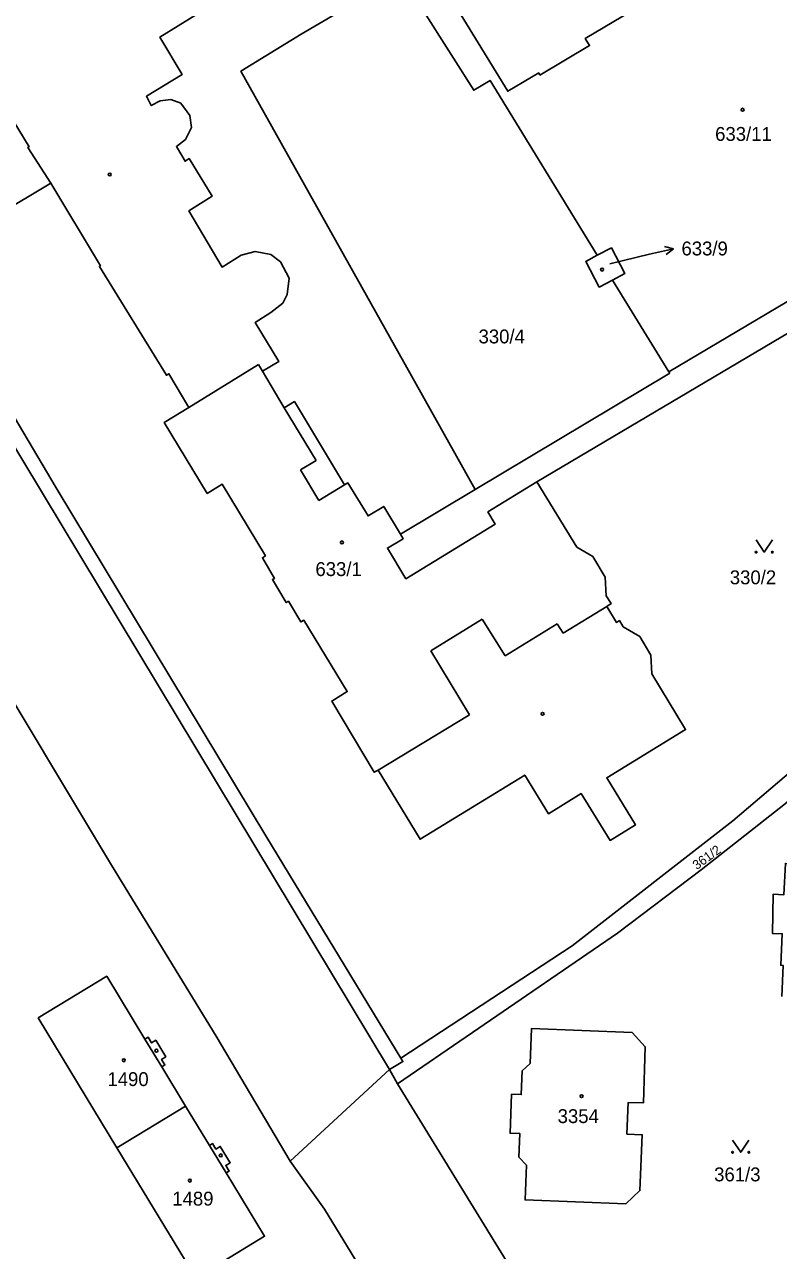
# Model space of a CAD drawing. Extents: x -679220 to -673243, y -1075091 to -1066557.
# Drawn here: x -675835 to -675742.5, y -1072476.3 to -1072325.9 of the extents above; entities that cross this region are included whole.
import ezdxf

# ---------------------------------------------------------------- set-up
doc = ezdxf.new("R2010")
doc.units = 0
for name, color, linetype in [('Hranice parcel', 7, 'Continuous'), ('Parcelní čísla', 7, 'Continuous'), ('Pop  PČ popisy', 7, 'Continuous'), ('Vnitřní kresba', 7, 'Continuous'), ('Značky budov', 7, 'Continuous'), ('Značky kultur', 7, 'Continuous')]:
    doc.layers.add(name, color=color, linetype=linetype)

msp = doc.modelspace()

# ---------------------------------------------------------------- linework, layer by layer
at = {"layer": 'Hranice parcel'}
for p, q in [((-675847.7, -1072354.86), (-675831.76, -1072345.39)), ((-675755.91, -1072368.55), (-675725.02, -1072350.17)), ((-675762.83, -1072357.28), (-675755.91, -1072368.55)), ((-675736.86, -1072361.17), (-675772.1, -1072382.03)), ((-675779.67, -1072382.96), (-675755.81, -1072368.71)), ((-675755.81, -1072368.71), (-675755.91, -1072368.55)), ((-675788.85, -1072388.44), (-675779.67, -1072382.96)), ((-675802.38, -1072465.38), (-675790.19, -1072454.14)), ((-675790.19, -1072454.14), (-675789.23, -1072455.87)), ((-675815.23, -1072458.61), (-675823.65, -1072463.72)), ((-675813.96, -1072479.68), (-675823.65, -1072463.72))]:
    msp.add_line(p, q, dxfattribs=at)
for points in [[(-675990.34, -1072122.74), (-675965.06, -1072164.5), (-675944.22, -1072198.66), (-675920.45, -1072238.88), (-675899.68, -1072273.04), (-675879.13, -1072306.74), (-675849.47, -1072355.79), (-675790.19, -1072454.14)], [(-675826.14, -1072308.69), (-675826.56, -1072309.22), (-675827.19, -1072309.93), (-675827.57, -1072310.88), (-675827.69, -1072311.75), (-675827.52, -1072312.73), (-675827.33, -1072313.58), (-675827.04, -1072314.06), (-675844.34, -1072324.49), (-675839.1, -1072333.23), (-675839.42, -1072333.42), (-675837.28, -1072336.95), (-675836.95, -1072336.77), (-675834.44, -1072340.93), (-675834.58, -1072341.01), (-675831.76, -1072345.39)], [(-675771.74, -1072332.13), (-675771.88, -1072331.88), (-675775.68, -1072334.13), (-675782.18, -1072323.54), (-675770.47, -1072316.51), (-675770.14, -1072317.05), (-675763.67, -1072313.14), (-675762.01, -1072315.74), (-675756.31, -1072312.33), (-675755.8, -1072313.14), (-675751.43, -1072310.59), (-675747.8, -1072316.66), (-675752.12, -1072319.31), (-675751.64, -1072320.13), (-675757.74, -1072323.78), (-675758.24, -1072322.9), (-675766.17, -1072327.66), (-675765.65, -1072328.52), (-675771.74, -1072332.13)], [(-675779.67, -1072382.96), (-675808.43, -1072331.67), (-675801.04, -1072327.14), (-675788.52, -1072319.77)], [(-675813.87, -1072324.69), (-675818.38, -1072327.47), (-675815.63, -1072332.06), (-675820.04, -1072334.74), (-675819.45, -1072335.88), (-675818.34, -1072335.31), (-675817.03, -1072335.13), (-675815.82, -1072335.58), (-675814.69, -1072337.1), (-675814.51, -1072338.55), (-675815.25, -1072340.06), (-675816.35, -1072340.91), (-675815.3, -1072342.71), (-675814.79, -1072342.39), (-675811.96, -1072346.98), (-675814.81, -1072348.8), (-675810.74, -1072355.7), (-675808.42, -1072354.25), (-675806.68, -1072353.78), (-675804.75, -1072354.16), (-675803.58, -1072355.05), (-675802.53, -1072357.04), (-675802.76, -1072359.06), (-675803.3, -1072360.11), (-675804.76, -1072361.28), (-675806.67, -1072362.48), (-675803.77, -1072367.26), (-675805.79, -1072368.46), (-675803.13, -1072372.94), (-675801.86, -1072372.18), (-675795.73, -1072382.42), (-675795.31, -1072382.17), (-675792.82, -1072386.21), (-675790.9, -1072385.04), (-675788.85, -1072388.44)], [(-675785.98, -1072324.32), (-675779.85, -1072333.99), (-675777.86, -1072332.8), (-675764.69, -1072354.25)], [(-675831.76, -1072345.39), (-675825.68, -1072355.53), (-675825.8, -1072355.6), (-675817.58, -1072368.95), (-675817.27, -1072368.77), (-675814.82, -1072372.9), (-675817.84, -1072374.76), (-675812.57, -1072383.46), (-675810.72, -1072382.32), (-675805.43, -1072391.12), (-675805.8, -1072391.34), (-675804.33, -1072393.89), (-675804.58, -1072394.03), (-675802.88, -1072396.84), (-675802.61, -1072396.68), (-675801.07, -1072399.22), (-675800.7, -1072399.01), (-675795.39, -1072407.77), (-675797.29, -1072408.92), (-675792.07, -1072417.66), (-675791.6, -1072417.4), (-675786.45, -1072425.87), (-675773.59, -1072418.01), (-675770.69, -1072422.74), (-675766.69, -1072420.27), (-675763.13, -1072426.02), (-675760.02, -1072424.11), (-675763.54, -1072418.34), (-675753.85, -1072412.43), (-675758.02, -1072405.57), (-675758.13, -1072403.28), (-675759.49, -1072401.01), (-675761.5, -1072399.81), (-675761.98, -1072399.05), (-675762.34, -1072399.27), (-675763.54, -1072397.31), (-675763, -1072396.97), (-675763.59, -1072396), (-675763.72, -1072393.72), (-675765.25, -1072391.19), (-675767.22, -1072390.03), (-675772.1, -1072382.03)], [(-675764.69, -1072354.25), (-675762.97, -1072353.34), (-675761.31, -1072356.47), (-675762.83, -1072357.28)], [(-675788.79, -1072452.73), (-675805.27, -1072425.65), (-675831.1, -1072382.79), (-675847.7, -1072354.86)], [(-675762.83, -1072357.28), (-675764.45, -1072358.14), (-675766.12, -1072355), (-675764.69, -1072354.25)], [(-675857.47, -1072373.89), (-675824.32, -1072429.06), (-675811.48, -1072450.02), (-675802.38, -1072465.38)], [(-675772.1, -1072382.03), (-675778.12, -1072385.73), (-675777.22, -1072387.22), (-675788.19, -1072393.93), (-675790.45, -1072390.17), (-675788.51, -1072389.01), (-675788.85, -1072388.44)], [(-675732.43, -1072410.33), (-675748.06, -1072423.6), (-675767.77, -1072438.97), (-675788.79, -1072452.73)], [(-675789.23, -1072455.87), (-675780.02, -1072449.59), (-675762.22, -1072437.39), (-675751.96, -1072429.64), (-675741.8, -1072421.67), (-675730.93, -1072412.45)], [(-675742.04, -1072445.16), (-675741.88, -1072441.35), (-675742.18, -1072441.34), (-675742, -1072437.47), (-675743.2, -1072437.42), (-675743.09, -1072432.61), (-675741.79, -1072432.68), (-675741.61, -1072428.84), (-675740.18, -1072428.89), (-675740.11, -1072426.41), (-675738.38, -1072424.77), (-675737.88, -1072424.79), (-675737.83, -1072423.59), (-675737.53, -1072423.6), (-675737.57, -1072424.78), (-675727.05, -1072425.19), (-675725.53, -1072426.86), (-675725.6, -1072429.62), (-675724.94, -1072429.73), (-675725.49, -1072441.79), (-675726.05, -1072441.77), (-675726.21, -1072445.79)], [(-675823.65, -1072463.72), (-675833.32, -1072447.79), (-675824.9, -1072442.68), (-675820.21, -1072450.41), (-675819.82, -1072450.17), (-675819.41, -1072450.85), (-675818.9, -1072450.54), (-675817.67, -1072452.56), (-675818.18, -1072452.88), (-675817.77, -1072453.56), (-675818.15, -1072453.79), (-675815.23, -1072458.61)], [(-675773.4, -1072465.86), (-675774.31, -1072464.88), (-675774.2, -1072461.99), (-675775.4, -1072461.95), (-675775.21, -1072457.15), (-675774.03, -1072457.19), (-675773.91, -1072454.29), (-675772.93, -1072453.37), (-675772.77, -1072449.11), (-675760.4, -1072449.6), (-675758.8, -1072451.32), (-675759.02, -1072458.2), (-675760.9, -1072458.15), (-675761.06, -1072462.04), (-675759.18, -1072462.12), (-675759.46, -1072468.97), (-675761.2, -1072470.6), (-675773.56, -1072470.12), (-675773.4, -1072465.86)], [(-675790.19, -1072454.14), (-675788.56, -1072453.14), (-675788.79, -1072452.73)], [(-675789.23, -1072455.87), (-675764.41, -1072496.19), (-675756.04, -1072510.12), (-675752.3, -1072515.97)], [(-675815.23, -1072458.61), (-675812.3, -1072463.43), (-675811.92, -1072463.2), (-675811.51, -1072463.88), (-675810.97, -1072463.55), (-675809.75, -1072465.56), (-675810.29, -1072465.89), (-675809.87, -1072466.58), (-675810.25, -1072466.81), (-675805.54, -1072474.57), (-675811.24, -1072478.03)], [(-675802.38, -1072465.38), (-675798.17, -1072471.25), (-675791.64, -1072481.95)]]:
    msp.add_lwpolyline(points, dxfattribs=at)
at = {"layer": 'Pop  PČ popisy'}
for p, q in [((-675758.28, -1072354.11), (-675755.36, -1072353.44)), ((-675755.36, -1072353.44), (-675756.44, -1072353.17)), ((-675755.36, -1072353.44), (-675756.22, -1072354.15)), ((-675763.15, -1072355.28), (-675758.28, -1072354.11))]:
    msp.add_line(p, q, dxfattribs=at)
at = {"layer": 'Vnitřní kresba'}
for p, q in [((-675814.82, -1072372.9), (-675806.28, -1072367.64)), ((-675806.28, -1072367.64), (-675805.79, -1072368.46)), ((-675799.19, -1072379.42), (-675803.13, -1072372.94)), ((-675801.11, -1072380.58), (-675799.19, -1072379.42)), ((-675798.86, -1072384.31), (-675801.11, -1072380.58)), ((-675795.73, -1072382.42), (-675798.86, -1072384.31)), ((-675763.54, -1072397.31), (-675768.9, -1072400.61)), ((-675778.83, -1072398.9), (-675785.11, -1072402.77)), ((-675776, -1072403.38), (-675778.83, -1072398.9)), ((-675769.61, -1072399.46), (-675776, -1072403.38)), ((-675768.9, -1072400.61), (-675769.61, -1072399.46)), ((-675785.11, -1072402.77), (-675780.38, -1072410.62)), ((-675780.38, -1072410.62), (-675791.6, -1072417.4)), ((-675820.21, -1072450.41), (-675818.15, -1072453.79)), ((-675812.3, -1072463.43), (-675810.25, -1072466.81))]:
    msp.add_line(p, q, dxfattribs=at)
at = {"layer": 'Značky budov'}
for centre in [(-675746.86, -1072336.39), (-675824.54, -1072344.33), (-675764.11, -1072356), (-675796.04, -1072389.46), (-675771.41, -1072410.5), (-675818.81, -1072451.81), (-675822.81, -1072452.99), (-675766.62, -1072457.39), (-675810.92, -1072464.66), (-675814.7, -1072467.75)]:
    msp.add_circle(centre, 0.175, dxfattribs=at)
at = {"layer": 'Značky kultur'}
for points in [[(-675745.2, -1072389.16), (-675744.2, -1072390.66), (-675743.2, -1072389.16)], [(-675748.09, -1072462.77), (-675747.09, -1072464.27), (-675746.09, -1072462.77)]]:
    msp.add_lwpolyline(points, dxfattribs=at)
for centre in [(-675745.2, -1072390.66), (-675743.2, -1072390.66), (-675748.09, -1072464.27), (-675746.09, -1072464.27)]:
    msp.add_circle(centre, 0.1, dxfattribs=at)

# ---------------------------------------------------------------- texts
at = {"layer": 'Parcelní čísla'}
for s, p in [('633/11', (-675750.23, -1072340.21)), ('633/9', (-675754.36, -1072354.26)), ('330/4', (-675779.27, -1072365.05)), ('633/1', (-675799.29, -1072393.59)), ('330/2', (-675748.43, -1072394.6)), ('1490', (-675824.82, -1072456.15)), ('3354', (-675769.56, -1072460.69)), ('361/3', (-675750.35, -1072467.84)), ('1489', (-675816.86, -1072470.81))]:
    msp.add_text(s, height=1.7, dxfattribs=at).set_placement(p)
msp.add_text('361/2', height=1.14, rotation=36, dxfattribs=at).set_placement((-675752.48, -1072429.67))

doc.saveas('drawing.dxf')
